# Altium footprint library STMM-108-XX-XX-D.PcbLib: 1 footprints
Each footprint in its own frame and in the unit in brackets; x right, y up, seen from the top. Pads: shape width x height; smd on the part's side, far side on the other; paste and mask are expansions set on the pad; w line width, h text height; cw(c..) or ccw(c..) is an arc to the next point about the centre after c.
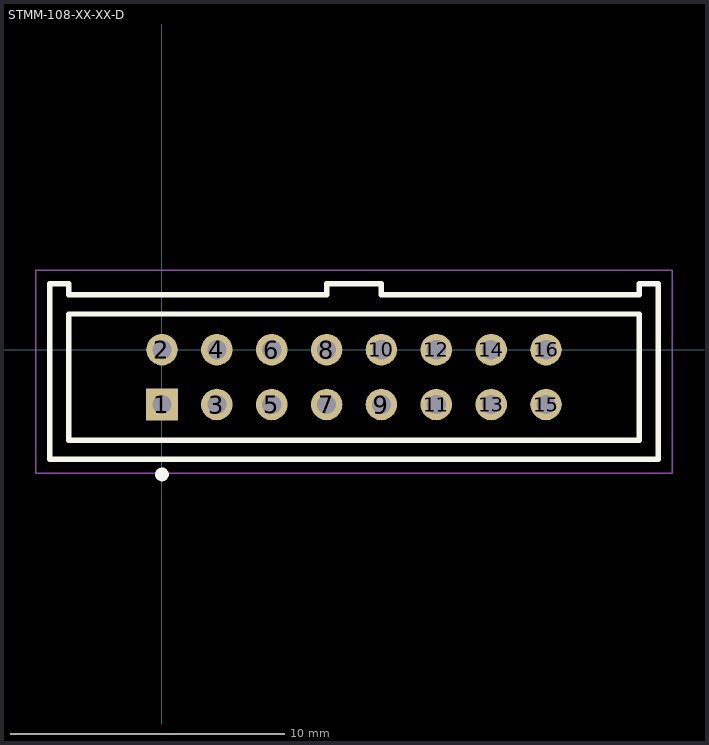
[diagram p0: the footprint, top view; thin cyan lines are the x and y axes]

## STMM-108-XX-XX-D [mm] "2.00mm pitch, 16 pin, header; shrouded"
height 4.8
pads (16):
  rect 1.15x1.15 / inner round 1.15 / far side rect 1.15x1.15 hole 0.7 mask+0: 1(0,-2)
  round 1.15 hole 0.7 mask+0: 2(0,0) 3(2,-2) 4(2,0) 5(4,-2) 6(4,0) 7(6,-2) 8(6,0) 9(8,-2) 10(8,0) 11(10,-2) 12(10,0) 13(12,-2) 14(12,0) 15(14,-2) 16(14,0)
Top Overlay:
  circle w0.25: c0,-4.55 r0.125
  lines w0.2: -4.1,-4 -4.1,2.4 -3.4,2.4 -3.4,2 6,2 6,2.4 8,2.4 8,2 17.4,2 17.4,2.4 18.1,2.4 18.1,-4 -4.1,-4 ; -3.4,-3.3 17.4,-3.3 17.4,1.3 -3.4,1.3 -3.4,-3.3
Mechanical 12:
  lines w0.001: -4.1,-4 -4.1,2.4 -3.4,2.4 -3.4,2 6,2 6,2.4 8,2.4 8,2 17.4,2 17.4,2.4 18.1,2.4 18.1,-4 -4.1,-4
Mechanical 13:
  lines w0.1: -4.1,-4 -4.1,2.4 -3.4,2.4 -3.4,2 6,2 6,2.4 8,2.4 8,2 17.4,2 17.4,2.4 18.1,2.4 18.1,-4 -4.1,-4 ; -3.4,-3.3 17.4,-3.3 17.4,1.3 -3.4,1.3 -3.4,-3.3
  text ".Designator" at 0,-2.127 h1.52
Mechanical 15:
  lines w0.05: -4.6,-4.5 18.6,-4.5 18.6,2.9 -4.6,2.9 -4.6,-4.5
